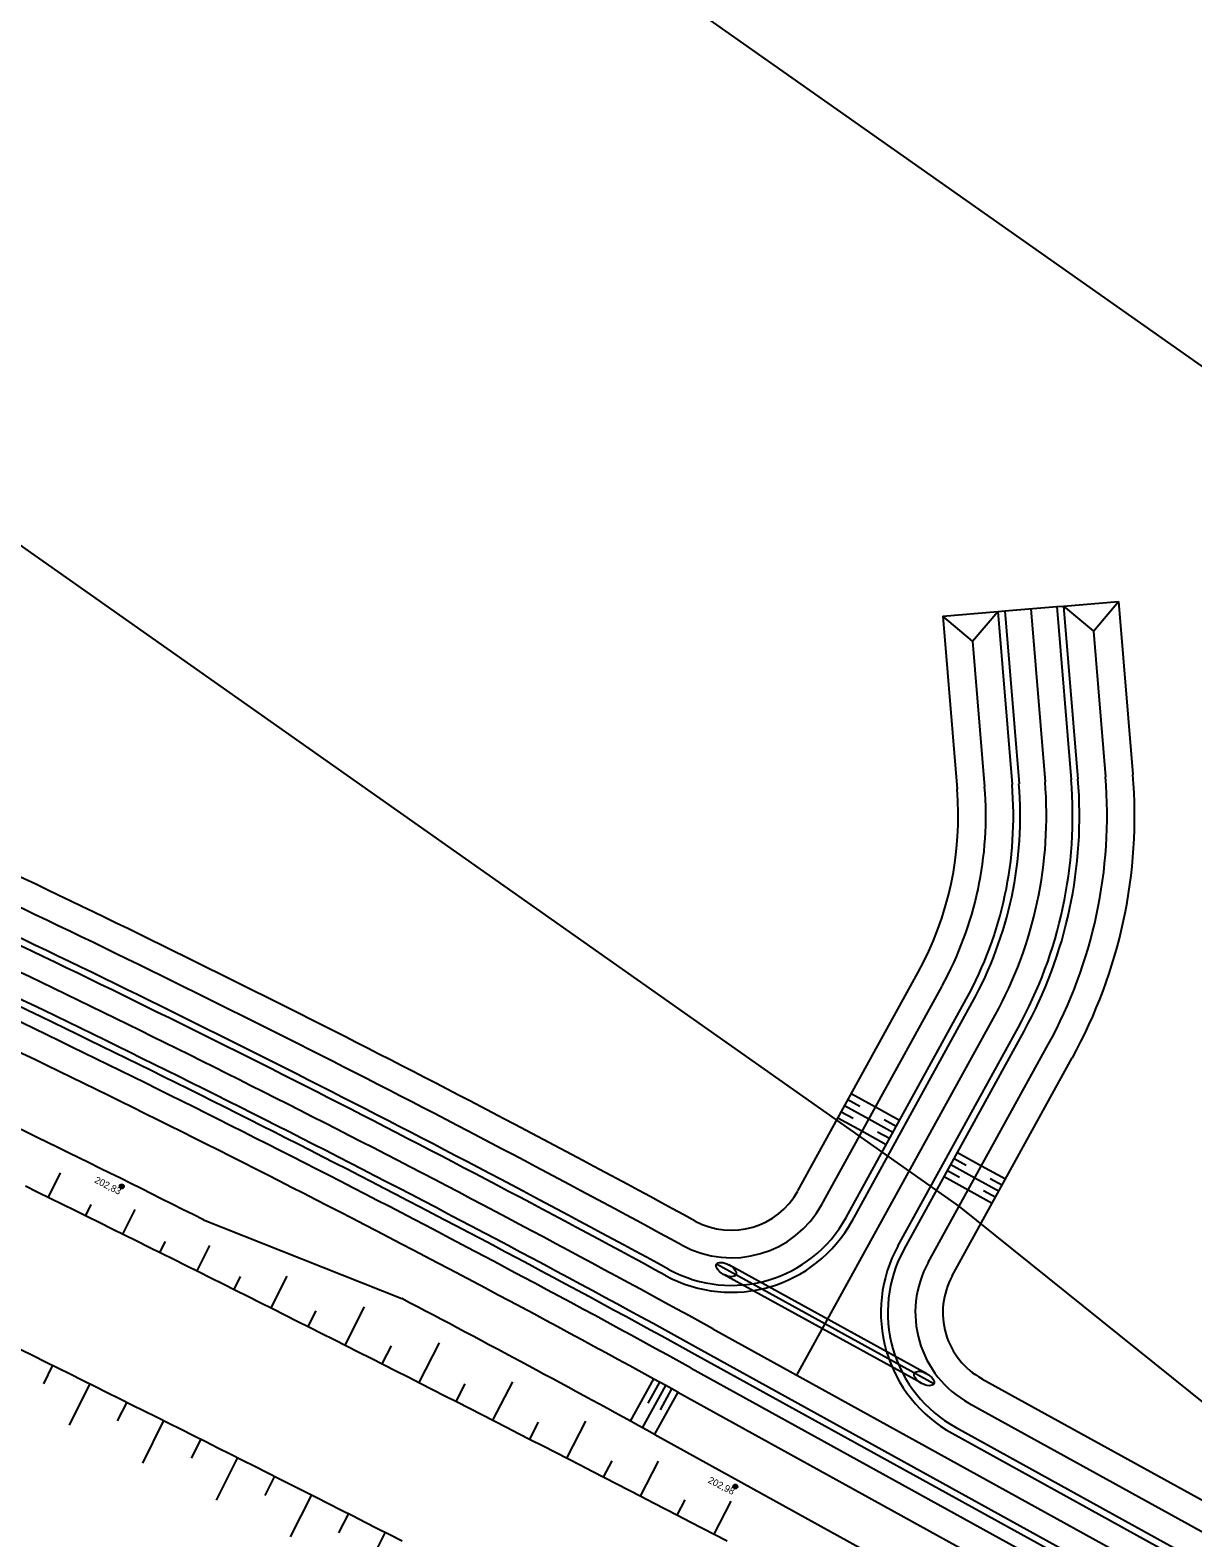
# Model space of a CAD drawing. Extents: x -551750 to -547457, y -1150683 to -1148508.
# Drawn here: x -550509.8 to -550425.4, y -1148936.3 to -1148826.9 of the extents above; entities that cross this region are included whole.
import ezdxf

# ---------------------------------------------------------------- set-up
doc = ezdxf.new("R2010")
doc.units = 0
for name, color, linetype in [('SO221815_VYSKOPIS', 7, 'Continuous'), ('u_ochranne_pasmo_CD', 7, 'Continuous'), ('u_trat navrh', 7, 'Continuous')]:
    doc.layers.add(name, color=color, linetype=linetype)

# ---------------------------------------------------------------- blocks, each defined once
blk = doc.blocks.new('SO221824_VYSKOPIS')
at = {"layer": 'SO221815_VYSKOPIS'}
for p, q in [((0.12, -0.09), (-0.12, 0.09)), ((0.09, 0.12), (-0.09, -0.12)), ((0.09, 0.12), (0, 0)), ((0, 0), (0.12, -0.09))]:
    blk.add_line(p, q, dxfattribs=at)
blk.add_lwpolyline([(-0.09, -0.12), (0, 0), (-0.12, 0.09)], dxfattribs=at)
blk.add_circle((0, 0), 0.15, dxfattribs=at)
for start, end in [(145.362, 235.1538), (325.362, 55.1538)]:
    blk.add_arc((0, 0), 0.15, start, end, dxfattribs=at)

msp = doc.modelspace()

# ---------------------------------------------------------------- linework, layer by layer
at = {"layer": 'u_ochranne_pasmo_CD'}
for points in [[(-551204.61, -1148514.47), (-551167.27, -1148510.53), (-551132.15, -1148508.58), (-551091.63, -1148508.39), (-551057.89, -1148509.37), (-551016.74, -1148513.63), (-550982.17, -1148519.49), (-550943.06, -1148529.96), (-550913.31, -1148538.83), (-550891.18, -1148546.58), (-550830.71, -1148571.43), (-550783.2, -1148596.84), (-550731.36, -1148628.54), (-550577.06, -1148738.92), (-550506.27, -1148793.92), (-550406.25, -1148864.3), (-550262.04, -1148980.17), (-550169.32, -1149047.69), (-550081.54, -1149120.02), (-549998.06, -1149180.27)], [(-551198.31, -1148574.14), (-551162.46, -1148570.35), (-551130.35, -1148568.57), (-551092.37, -1148568.39), (-551061.86, -1148569.28), (-551024.85, -1148573.11), (-550994.97, -1148578.18), (-550959.39, -1148587.7), (-550931.82, -1148595.92), (-550912.51, -1148602.68), (-550895.52, -1148609.67), (-550856.33, -1148625.77), (-550813.03, -1148648.94), (-550764.5, -1148678.6), (-550612.94, -1148787.03), (-550541.96, -1148842.17), (-550442.34, -1148912.27), (-550342.72, -1148992.32), (-550298.52, -1149027.84), (-550206.09, -1149095.14), (-550118.21, -1149167.54), (-550033.18, -1149228.92)]]:
    msp.add_lwpolyline(points, dxfattribs=at)
at = {"layer": 'u_trat navrh'}
for p, q in [((-550434.76, -1148868.7), (-550430.77, -1148868.37)), ((-550432.6, -1148870.52), (-550430.77, -1148868.37)), ((-550430.77, -1148868.37), (-550429.73, -1148880.92)), ((-550443.53, -1148869.42), (-550439.54, -1148869.09)), ((-550443.53, -1148869.42), (-550442.49, -1148881.98)), ((-550441.37, -1148871.25), (-550443.53, -1148869.42)), ((-550441.37, -1148871.25), (-550439.54, -1148869.09)), ((-550439.54, -1148869.09), (-550439.04, -1148869.05)), ((-550439.54, -1148869.09), (-550438.5, -1148881.65)), ((-550439.04, -1148869.05), (-550435.26, -1148868.74)), ((-550439.04, -1148869.05), (-550438, -1148881.61)), ((-550437.15, -1148868.89), (-550436.11, -1148881.45)), ((-550435.26, -1148868.74), (-550434.76, -1148868.7)), ((-550435.26, -1148868.74), (-550434.22, -1148881.3)), ((-550434.76, -1148868.7), (-550433.72, -1148881.25)), ((-550434.76, -1148868.7), (-550432.6, -1148870.52)), ((-550432.6, -1148870.52), (-550431.73, -1148881.09)), ((-550441.37, -1148871.25), (-550440.5, -1148881.81)), ((-550454.07, -1148911.15), (-550445.34, -1148895.31)), ((-550452.31, -1148912.12), (-550443.59, -1148896.28)), ((-550450.56, -1148913.08), (-550441.84, -1148897.24)), ((-550450.12, -1148913.33), (-550441.4, -1148897.48)), ((-550454.12, -1148924.52), (-550439.73, -1148898.4)), ((-550446.79, -1148915.15), (-550438.07, -1148899.32)), ((-550446.35, -1148915.39), (-550437.63, -1148899.56)), ((-550444.6, -1148916.35), (-550435.88, -1148900.52)), ((-550442.85, -1148917.32), (-550434.13, -1148901.49)), ((-550449.55, -1148905.02), (-550450.42, -1148904.54)), ((-550448.43, -1148905.07), (-550450.18, -1148904.1)), ((-550449.4, -1148906.82), (-550451.15, -1148905.86)), ((-550450.03, -1148905.9), (-550450.91, -1148905.42)), ((-550448.91, -1148905.94), (-550450.66, -1148904.98)), ((-550446.68, -1148906.03), (-550448.43, -1148905.07)), ((-550447.64, -1148907.79), (-550449.4, -1148906.82)), ((-550447.16, -1148906.91), (-550448.91, -1148905.94)), ((-550447.4, -1148907.35), (-550448.28, -1148906.87)), ((-550446.92, -1148906.47), (-550447.8, -1148905.99)), ((-550442.72, -1148908.79), (-550441.84, -1148909.27)), ((-550442.47, -1148908.35), (-550440.72, -1148909.32)), ((-550508.45, -1148911.61), (-550507.58, -1148909.83)), ((-550443.44, -1148910.1), (-550441.69, -1148911.07)), ((-550443.2, -1148909.66), (-550442.32, -1148910.15)), ((-550442.96, -1148909.23), (-550441.2, -1148910.19)), ((-550441.2, -1148910.19), (-550439.45, -1148911.16)), ((-550440.72, -1148909.32), (-550438.97, -1148910.28)), ((-550440.09, -1148910.24), (-550439.21, -1148910.72)), ((-550441.69, -1148911.07), (-550439.94, -1148912.03)), ((-550440.57, -1148911.11), (-550439.69, -1148911.59)), ((-550505.76, -1148912.94), (-550505.36, -1148912.14)), ((-550503.06, -1148914.28), (-550502.18, -1148912.5)), ((-550497.21, -1148913.24), (-550482.81, -1148918.96)), ((-550500.37, -1148915.61), (-550499.97, -1148914.82)), ((-550497.67, -1148916.95), (-550496.75, -1148915.11)), ((-550444.19, -1148925.14), (-550459.96, -1148916.47)), ((-550444.7, -1148924.41), (-550459.07, -1148916.5)), ((-550494.98, -1148918.3), (-550494.51, -1148917.36)), ((-550492.29, -1148919.64), (-550491.13, -1148917.33)), ((-550445.08, -1148925.11), (-550459.45, -1148917.2)), ((-550489.6, -1148920.99), (-550489.03, -1148919.85)), ((-550486.92, -1148922.34), (-550485.51, -1148919.56)), ((-550460.23, -1148921.16), (-550253.98, -1149034.78)), ((-550481.55, -1148925.06), (-550480.08, -1148922.16)), ((-550484.23, -1148923.7), (-550483.56, -1148922.38)), ((-550461.07, -1148922.69), (-550254.82, -1149036.32)), ((-550508.16, -1148923.8), (-550508.83, -1148925.14)), ((-550461.8, -1148924.01), (-550255.55, -1149037.63)), ((-550505.47, -1148925.13), (-550506.97, -1148928.15)), ((-550478.87, -1148926.42), (-550478.21, -1148925.14)), ((-550476.19, -1148927.79), (-550474.76, -1148924.99)), ((-550464.54, -1148924.78), (-550466.22, -1148927.85)), ((-550463.66, -1148925.26), (-550465.35, -1148928.33)), ((-550464.1, -1148925.02), (-550464.94, -1148926.56)), ((-550463.22, -1148925.51), (-550464.06, -1148927.04)), ((-550440.69, -1148924.79), (-550379.29, -1148958.62)), ((-550502.78, -1148926.47), (-550503.47, -1148927.84)), ((-550462.78, -1148925.75), (-550464.47, -1148928.81)), ((-550462.76, -1148925.76), (-550256.51, -1149039.38)), ((-550441.65, -1148926.54), (-550251.93, -1149031.06)), ((-550500.1, -1148927.81), (-550501.64, -1148930.9)), ((-550473.51, -1148929.16), (-550472.88, -1148927.93)), ((-550470.83, -1148930.53), (-550469.46, -1148927.86)), ((-550464.45, -1148928.82), (-550344.48, -1148994.92)), ((-550442.86, -1148928.73), (-550253.14, -1149033.25)), ((-550442.62, -1148928.29), (-550252.89, -1149032.81)), ((-550497.41, -1148929.16), (-550498.11, -1148930.55)), ((-550494.73, -1148930.5), (-550496.29, -1148933.6)), ((-550468.16, -1148931.91), (-550467.55, -1148930.74)), ((-550465.48, -1148933.29), (-550464.18, -1148930.76)), ((-550492.05, -1148931.85), (-550492.75, -1148933.24)), ((-550489.37, -1148933.21), (-550490.91, -1148936.25)), ((-550462.81, -1148934.67), (-550462.24, -1148933.56)), ((-550460.14, -1148936.05), (-550458.9, -1148933.66)), ((-550486.69, -1148934.56), (-550487.4, -1148935.96)), ((-550484.01, -1148935.92), (-550485.64, -1148939.13))]:
    msp.add_line(p, q, dxfattribs=at)
for points in [[(-550510.13, -1148910.78), (-550509.23, -1148911.23), (-550508.34, -1148911.67), (-550507.44, -1148912.11), (-550506.54, -1148912.55), (-550505.64, -1148913), (-550504.74, -1148913.44), (-550503.85, -1148913.89), (-550502.95, -1148914.33), (-550502.05, -1148914.77), (-550501.15, -1148915.22), (-550500.26, -1148915.67), (-550499.36, -1148916.11), (-550498.47, -1148916.56), (-550497.57, -1148917), (-550496.67, -1148917.45), (-550495.78, -1148917.9), (-550494.88, -1148918.35), (-550493.99, -1148918.79), (-550493.09, -1148919.24), (-550492.19, -1148919.69), (-550491.3, -1148920.14), (-550490.4, -1148920.59), (-550489.51, -1148921.04), (-550488.62, -1148921.49), (-550487.72, -1148921.94), (-550486.83, -1148922.39), (-550485.93, -1148922.84), (-550485.04, -1148923.29), (-550484.15, -1148923.74), (-550483.25, -1148924.2), (-550482.36, -1148924.65), (-550481.47, -1148925.1), (-550480.57, -1148925.56), (-550479.68, -1148926.01), (-550478.79, -1148926.46), (-550477.9, -1148926.92), (-550477, -1148927.37), (-550476.11, -1148927.83), (-550475.22, -1148928.28), (-550474.33, -1148928.74), (-550473.44, -1148929.2), (-550472.55, -1148929.65), (-550471.65, -1148930.11), (-550470.76, -1148930.57), (-550469.87, -1148931.02), (-550468.98, -1148931.48), (-550468.09, -1148931.94), (-550467.2, -1148932.4), (-550466.31, -1148932.86), (-550465.42, -1148933.32), (-550464.53, -1148933.78), (-550463.64, -1148934.24), (-550462.75, -1148934.7), (-550461.87, -1148935.16), (-550460.98, -1148935.62), (-550460.09, -1148936.08), (-550459.2, -1148936.54)], [(-550510.46, -1148922.66), (-550509.57, -1148923.1), (-550508.67, -1148923.55), (-550507.78, -1148923.99), (-550506.88, -1148924.43), (-550505.99, -1148924.88), (-550505.09, -1148925.32), (-550504.2, -1148925.77), (-550503.3, -1148926.21), (-550502.41, -1148926.66), (-550501.52, -1148927.1), (-550500.62, -1148927.55), (-550499.73, -1148928), (-550498.84, -1148928.44), (-550497.94, -1148928.89), (-550497.05, -1148929.34), (-550496.16, -1148929.78), (-550495.27, -1148930.23), (-550494.37, -1148930.68), (-550493.48, -1148931.13), (-550492.59, -1148931.58), (-550491.7, -1148932.03), (-550490.81, -1148932.48), (-550489.91, -1148932.93), (-550489.02, -1148933.38), (-550488.13, -1148933.83), (-550487.24, -1148934.28), (-550486.35, -1148934.73), (-550485.46, -1148935.19), (-550484.57, -1148935.64), (-550483.68, -1148936.09), (-550482.79, -1148936.55)], [(-550255.07, -1149036.76), (-550461.31, -1148923.13)]]:
    msp.add_lwpolyline(points, dxfattribs=at)
for centre, radius, start, end in [((-550466.01, -1148883.92), 25.6, 331.1494, 4.7277), ((-550466.01, -1148883.92), 27.6, 331.1494, 4.7277), ((-550466.01, -1148883.92), 28.1, 331.1494, 4.7277), ((-550466.01, -1148883.92), 30, 331.1494, 4.7277), ((-550466.01, -1148883.92), 31.9, 331.1494, 4.7277), ((-550466.01, -1148883.92), 32.4, 331.1494, 4.7277), ((-550466.01, -1148883.92), 34.4, 331.1494, 4.7277), ((-550466.01, -1148883.92), 36.4, 331.1494, 4.7277), ((-550466.01, -1148883.92), 23.6, 331.1494, 4.7277), ((-550942.76, -1149797.04), 1006.25, 61.42863, 64.80614), ((-550942.76, -1149797.04), 1004.25, 61.42863, 64.80614), ((-550942.76, -1149797.04), 1002.25, 61.42863, 64.80614), ((-550942.76, -1149797.04), 1001.75, 61.42863, 64.80614), ((-550942.76, -1149797.04), 1000, 61.14938, 64.80614), ((-550942.76, -1149797.04), 998.25, 61.14938, 64.80614), ((-550942.76, -1149797.04), 997.75, 61.14938, 64.80614), ((-550942.76, -1149797.04), 996.75, 61.14938, 64.80614), ((-550942.76, -1149797.04), 994.75, 61.14938, 64.80614), ((-550942.76, -1149797.04), 989.75, 63.24626, 64.80614), ((-550458.88, -1148908.5), 5.5, 241.4286, 331.1494), ((-550458.88, -1148908.5), 7.5, 241.4286, 331.1494), ((-550458.88, -1148908.5), 10, 241.4286, 331.1494), ((-550458.88, -1148908.5), 9.5, 241.4286, 331.1494), ((-550438.03, -1148919.97), 10, 151.1494, 241.1494), ((-550438.03, -1148919.97), 9.5, 151.1494, 241.1494), ((-550438.03, -1148919.97), 7.5, 151.1494, 241.1494), ((-550438.03, -1148919.97), 5.5, 151.1494, 241.1494), ((-550942.76, -1149797.04), 991.25, 61.14938, 62.35437)]:
    msp.add_arc(centre, radius, start, end, dxfattribs=at)
for centre, ratio in [((-550459.26, -1148916.85), 0.5), ((-550444.89, -1148924.76), 0.500013)]:
    msp.add_ellipse(centre, major_axis=(0.701, -0.386), ratio=ratio, dxfattribs=at)

# ---------------------------------------------------------------- block references
at = {"layer": 'u_trat navrh', "rotation": -31.851985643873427}
for p in [(-550503.14, -1148910.82), (-550458.6, -1148932.6)]:
    msp.add_blockref('SO221824_VYSKOPIS', p, dxfattribs=at)

# ---------------------------------------------------------------- texts
at = {"layer": 'u_trat navrh'}
for s, p in [('202,83', (-550505.17, -1148910.52)), ('202,98', (-550460.63, -1148932.3))]:
    msp.add_text(s, height=0.5, rotation=333.2568, dxfattribs=at).set_placement(p)

doc.saveas('drawing.dxf')
